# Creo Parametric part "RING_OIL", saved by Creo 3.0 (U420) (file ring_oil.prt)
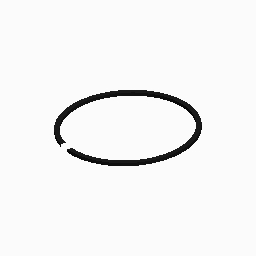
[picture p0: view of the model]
Units: millimeter Kilogram Sec (mmKs); MM, KILOGRAM, SECS

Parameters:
  MATERIAL = "GOE 32"

Created from: INLBS_PART_SOLID.PRT

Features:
  1. coordinate system "ORIGIN"
  2. datum plane "SIDE", "RIGHT"
  3. datum plane "DTM1", "TOP"
  4. datum plane "DTM2", "FRONT"
  5. datum axis "RING_AXIS"
  6. extrusion "Extrude 1"
  7. extruded cut "Extrude 2"

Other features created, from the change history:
  group "COPIED_GROUP"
